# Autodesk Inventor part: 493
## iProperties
Author: Administrator
Shininess: 64.0
Angle Display Precision: 2
Document Length Units: 11272
Document Angle Units: 11286
Document Time Units: 11279
Document Mass Units: 11290
Document Length Units Precision: 3
Document Angle Units Precision: 2
Compacted: True
PropertySet Name: _Private Model Information
Created: 2002-03
Part Number: 493
Material: Stainless Steel, 440C
Document SubType Name: Modeling
Designer: Administrator
Control State: 0
Master: False
Checked Out: False
PropertySet Name: Design Tracking Control
Density: 0.0
Volumn: 0.0
Area: 0.0
PropertySet Name: Model Information
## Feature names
1. Revolution1
